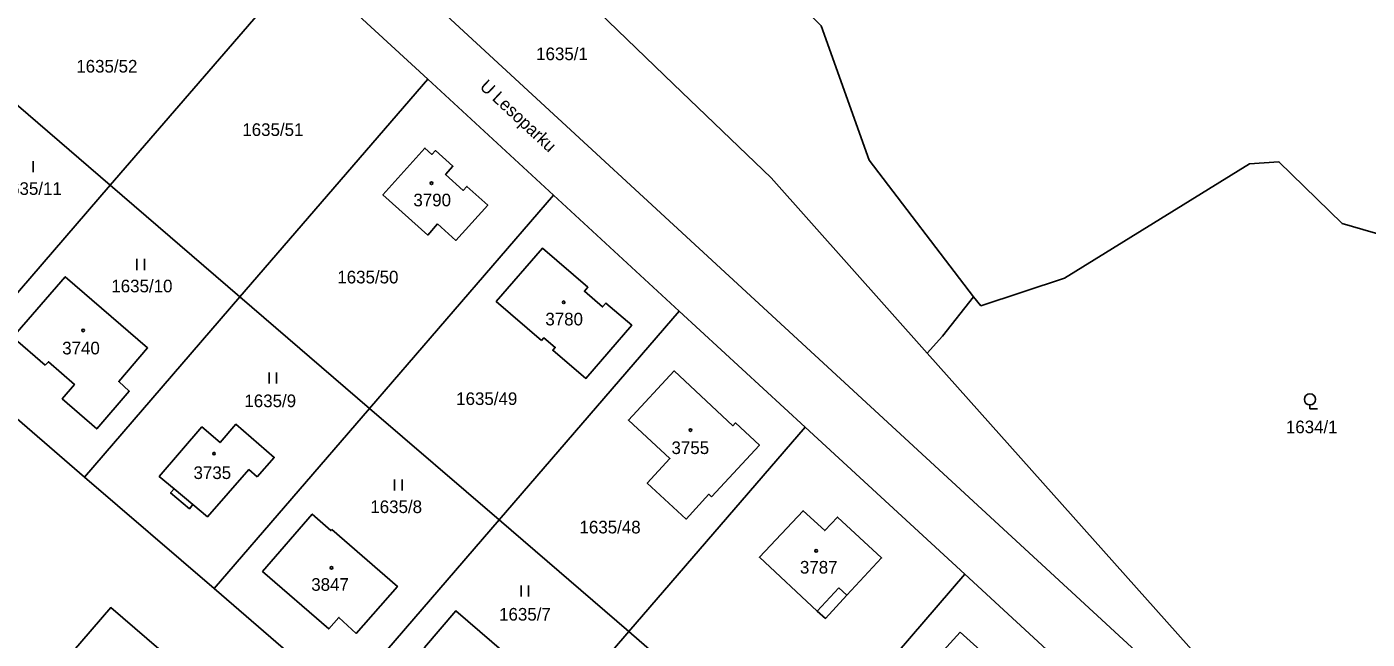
# Model space of a CAD drawing. Extents: x -679220 to -673243, y -1075091 to -1066557.
# Drawn here: x -677199.8 to -677019.6, y -1071775.1 to -1071692.7 of the extents above; entities that cross this region are included whole.
import ezdxf

# ---------------------------------------------------------------- set-up
doc = ezdxf.new("R2010")
doc.units = 0
for name, color, linetype in [('Hranice parcel', 7, 'Continuous'), ('Parcelní čísla', 7, 'Continuous'), ('Pop  PČ popisy', 7, 'Continuous'), ('Vnitřní kresba', 7, 'Continuous'), ('Značky budov', 7, 'Continuous'), ('Značky kultur', 7, 'Continuous')]:
    doc.layers.add(name, color=color, linetype=linetype)

msp = doc.modelspace()

# ---------------------------------------------------------------- linework, layer by layer
at = {"layer": 'Hranice parcel'}
for p, q in [((-677162.84, -1071684.18), (-677188.6, -1071714.05)), ((-677145.92, -1071699.77), (-677162.84, -1071684.18)), ((-677188.6, -1071714.05), (-677206.02, -1071699.04)), ((-677145.92, -1071699.77), (-677171.17, -1071729.06)), ((-677129.02, -1071715.37), (-677145.92, -1071699.77)), ((-677188.6, -1071714.05), (-677209.5, -1071738.28)), ((-677171.17, -1071729.06), (-677188.6, -1071714.05)), ((-677129.02, -1071715.37), (-677153.75, -1071744.07)), ((-677112.11, -1071730.97), (-677129.02, -1071715.37)), ((-677171.17, -1071729.06), (-677192.07, -1071753.3)), ((-677153.75, -1071744.07), (-677171.17, -1071729.06)), ((-677112.11, -1071730.97), (-677136.33, -1071759.08)), ((-677095.19, -1071746.58), (-677112.11, -1071730.97)), ((-677192.07, -1071753.3), (-677209.5, -1071738.28)), ((-677153.75, -1071744.07), (-677174.65, -1071768.31)), ((-677136.33, -1071759.08), (-677153.75, -1071744.07)), ((-677095.19, -1071746.58), (-677118.9, -1071774.1)), ((-677073.73, -1071766.37), (-677095.19, -1071746.58)), ((-677174.65, -1071768.31), (-677192.07, -1071753.3)), ((-677136.33, -1071759.08), (-677157.23, -1071783.32)), ((-677118.9, -1071774.1), (-677136.33, -1071759.08)), ((-677073.73, -1071766.37), (-677096.78, -1071793.16)), ((-677051.64, -1071786.74), (-677073.73, -1071766.37)), ((-677157.23, -1071783.32), (-677174.65, -1071768.31)), ((-677118.9, -1071774.1), (-677139.8, -1071798.34)), ((-677101.48, -1071789.11), (-677118.9, -1071774.1))]:
    msp.add_line(p, q, dxfattribs=at)
for points in [[(-677072.54, -1071729.05), (-677086.59, -1071710.67), (-677093.03, -1071692.61), (-677130.34, -1071655.44), (-677135.83, -1071648.8), (-677133.83, -1071641.99), (-677130.78, -1071626.26), (-677124.98, -1071617.49)], [(-677203.81, -1071626.06), (-677205.28, -1071627.7), (-677204.89, -1071634.52), (-677143.42, -1071691.21), (-677025.94, -1071799.59)], [(-677203.81, -1071626.06), (-677197.92, -1071629.89), (-677173.19, -1071646.04), (-677157.32, -1071658.82), (-677152.38, -1071663.28), (-677139.17, -1071675), (-677112.89, -1071700.45), (-677099.77, -1071713.06), (-677078.77, -1071736.63)], [(-676981.66, -1071694.34), (-676988.54, -1071702.17), (-677007.4, -1071718.46), (-677015.75, -1071721.28), (-677022.98, -1071719.19), (-677031.5, -1071710.88), (-677035.45, -1071711.18), (-677060.3, -1071726.54), (-677071.55, -1071730.26), (-677072.54, -1071729.05)], [(-677144.59, -1071719.25), (-677145.93, -1071720.74), (-677151.95, -1071715.32), (-677146.3, -1071709.05), (-677145.39, -1071709.9), (-677144.88, -1071709.37), (-677142.53, -1071711.48), (-677143.53, -1071712.59), (-677141.15, -1071714.74), (-677140.65, -1071714.2), (-677137.85, -1071716.71), (-677142.13, -1071721.47), (-677144.59, -1071719.25)], [(-677130.63, -1071734.94), (-677136.71, -1071729.68), (-677130.51, -1071722.51), (-677124.4, -1071727.77), (-677124.86, -1071728.31), (-677122.41, -1071730.42), (-677121.96, -1071729.89), (-677118.49, -1071732.88), (-677124.65, -1071740.03), (-677129.11, -1071736.25), (-677128.79, -1071735.87), (-677130.3, -1071734.56), (-677130.63, -1071734.94)], [(-677197.34, -1071738.27), (-677201.69, -1071734.49), (-677194.65, -1071726.36), (-677183.59, -1071735.94), (-677187.46, -1071740.46), (-677186.04, -1071741.73), (-677190.41, -1071746.83), (-677195.06, -1071742.78), (-677193.42, -1071740.84), (-677196.91, -1071737.79), (-677197.34, -1071738.27)], [(-677072.54, -1071729.05), (-677076.71, -1071734.36), (-677078.77, -1071736.63)], [(-677078.77, -1071736.63), (-677039.53, -1071780.68), (-677031.38, -1071788.86), (-677024.1, -1071793.73), (-677022.61, -1071794.93)], [(-677107.77, -1071755.97), (-677108.14, -1071755.63), (-677111.2, -1071758.95), (-677116.41, -1071754.12), (-677113.36, -1071750.83), (-677118.94, -1071745.64), (-677112.81, -1071739.02), (-677104.89, -1071746.4), (-677104.55, -1071746.03), (-677101.34, -1071749.01), (-677107.77, -1071755.97)], [(-677168.85, -1071753.29), (-677169.97, -1071752.31), (-677175.53, -1071758.65), (-677177.51, -1071757), (-677177.97, -1071757.56), (-677180.5, -1071755.45), (-677180.03, -1071754.88), (-677182.02, -1071753.22), (-677176.29, -1071746.55), (-677173.83, -1071748.66), (-677171.71, -1071746.19), (-677166.55, -1071750.67), (-677168.85, -1071753.29)], [(-677158.8, -1071760.35), (-677149.99, -1071768.01), (-677155.56, -1071774.35), (-677157.87, -1071772.2), (-677159.24, -1071773.74), (-677168.13, -1071766), (-677161.44, -1071758.28), (-677158.93, -1071760.5), (-677158.8, -1071760.35)], [(-677089.57, -1071769.22), (-677092.45, -1071772.32), (-677093.55, -1071771.34), (-677101.34, -1071764.1), (-677095.47, -1071757.84), (-677092.56, -1071760.51), (-677090.84, -1071758.69), (-677084.92, -1071764.18), (-677089.57, -1071769.22)], [(-677192, -1071810.12), (-677209.43, -1071795.1), (-677188.54, -1071770.86), (-677171.11, -1071785.87)], [(-677138.57, -1071791.51), (-677146.72, -1071784.47), (-677143.45, -1071780.64), (-677143.66, -1071778.61), (-677146.38, -1071776.26), (-677142.13, -1071771.3), (-677134.08, -1071778.28), (-677135.04, -1071779.42), (-677131.04, -1071782.79), (-677138.57, -1071791.51)], [(-677074.33, -1071774.18), (-677065.81, -1071781.9), (-677065.41, -1071781.46), (-677063.18, -1071783.48), (-677063.59, -1071783.92), (-677059.07, -1071788.02), (-677064.04, -1071793.5), (-677068.56, -1071789.4), (-677070, -1071790.99), (-677075.19, -1071786.29), (-677073.74, -1071784.7), (-677079.3, -1071779.66), (-677074.33, -1071774.18)]]:
    msp.add_lwpolyline(points, dxfattribs=at)
at = {"layer": 'Vnitřní kresba'}
for p, q in [((-677180.03, -1071754.88), (-677177.51, -1071757)), ((-677093.55, -1071771.34), (-677090.67, -1071768.21)), ((-677090.67, -1071768.21), (-677089.57, -1071769.22))]:
    msp.add_line(p, q, dxfattribs=at)
at = {"layer": 'Značky budov'}
for centre in [(-677145.41, -1071713.77), (-677127.64, -1071729.79), (-677192.24, -1071733.57), (-677110.59, -1071746.98), (-677174.66, -1071750.15), (-677093.7, -1071763.24), (-677158.86, -1071765.53)]:
    msp.add_circle(centre, 0.175, dxfattribs=at)
at = {"layer": 'Značky kultur'}
for p, q in [((-677198.95, -1071712.29), (-677198.95, -1071710.79)), ((-677185.02, -1071725.46), (-677185.02, -1071723.96)), ((-677184.02, -1071725.46), (-677184.02, -1071723.96)), ((-677167.25, -1071740.73), (-677167.25, -1071739.23)), ((-677166.25, -1071740.73), (-677166.25, -1071739.23)), ((-677027.33, -1071743.61), (-677027.33, -1071744.11)), ((-677027.33, -1071744.11), (-677026.33, -1071744.11)), ((-677150.38, -1071755.13), (-677150.38, -1071753.63)), ((-677149.38, -1071755.13), (-677149.38, -1071753.63)), ((-677133.38, -1071769.39), (-677133.38, -1071767.89)), ((-677132.38, -1071769.39), (-677132.38, -1071767.89))]:
    msp.add_line(p, q, dxfattribs=at)
msp.add_circle((-677027.33, -1071742.86), 0.75, dxfattribs=at)

# ---------------------------------------------------------------- texts
at = {"layer": 'Parcelní čísla'}
for s, p in [('1635/1', (-677131.35, -1071697.21)), ('1635/52', (-677193.17, -1071698.88)), ('1635/51', (-677170.85, -1071707.41)), ('1635/11', (-677203.33, -1071715.34)), ('3790', (-677147.85, -1071716.88)), ('1635/50', (-677158.08, -1071727.25)), ('1635/10', (-677188.46, -1071728.45)), ('3780', (-677130.11, -1071732.9)), ('3740', (-677195.06, -1071736.8)), ('1635/9', (-677170.57, -1071743.9)), ('1635/49', (-677142.1, -1071743.61)), ('1634/1', (-677030.56, -1071747.41)), ('3755', (-677113.15, -1071750.21)), ('3735', (-677177.41, -1071753.57)), ('1635/8', (-677153.64, -1071758.15)), ('1635/48', (-677125.52, -1071760.89)), ('3787', (-677095.89, -1071766.29)), ('3847', (-677161.58, -1071768.61)), ('1635/7', (-677136.33, -1071772.62))]:
    msp.add_text(s, height=1.7, dxfattribs=at).set_placement(p)
at = {"layer": 'Pop  PČ popisy'}
msp.add_text('U Lesoparku', height=1.7, rotation=317, dxfattribs=at).set_placement((-677139.04, -1071700.93))

doc.saveas('drawing.dxf')
